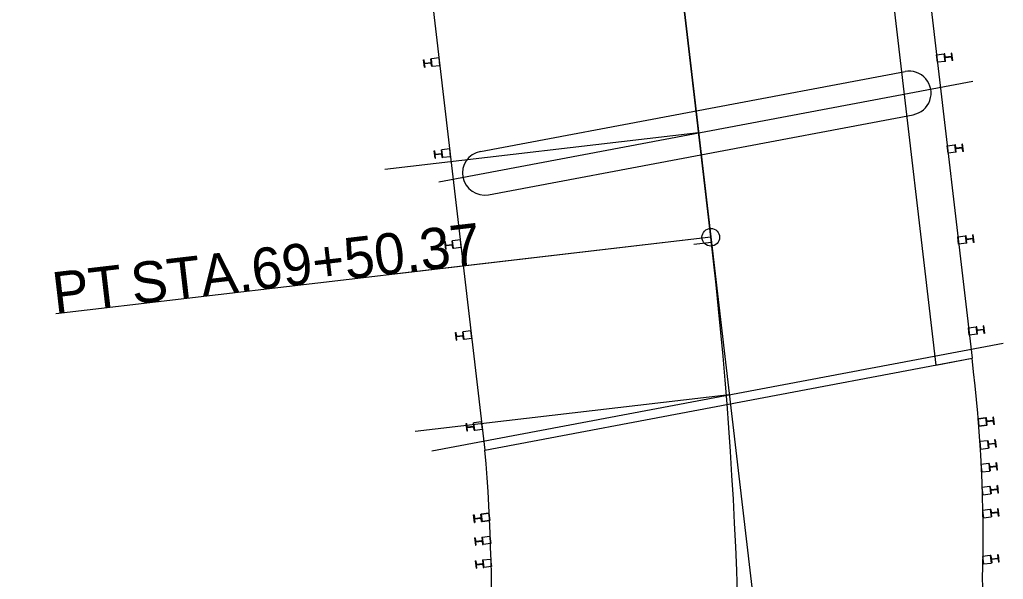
# Model space of a CAD drawing. Extents: x 27625 to 127752, y 6088 to 302357.
# Drawn here: x 127685.2 to 127752.3, y 301985 to 302023.2 of the extents above; entities that cross this region are included whole.
import ezdxf

# ---------------------------------------------------------------- set-up
doc = ezdxf.new("R2010")
doc.units = 0
for name, color, linetype in [('_CIVIL_CONSTRUCTION', 7, 'Continuous'), ('DR_X_Cells', 7, 'Continuous'), ('DV_X_Property_Line', 7, 'Continuous'), ('DV_X_Section_VMS_Line', 7, 'Continuous'), ('RW_X_CL', 7, 'Continuous'), ('RW_X_CL_100_Bearings', 7, 'Continuous'), ('RW_X_CL_100_Cardinal_Points', 7, 'Continuous'), ('RW_X_CL_100_Curve_Data', 7, 'Continuous'), ('RW_X_CL_100_Stations', 7, 'Continuous'), ('RW_X_Fee_RW', 7, 'Continuous'), ('SC_Scratch13', 7, 'Continuous'), ('SC_Scratch2', 7, 'Continuous'), ('SV_X_Mon_Cells_Found', 7, 'Continuous'), ('TopoDOT_Transients', 7, 'Continuous')]:
    doc.layers.add(name, color=color, linetype=linetype)

msp = doc.modelspace()

# ---------------------------------------------------------------- linework, layer by layer
at = {"layer": '_CIVIL_CONSTRUCTION'}
for p, q in [((127731.494, 302015.492), (127710.068, 302012.985)), ((127733.585, 301997.613), (127712.159, 301995.107))]:
    msp.add_line(p, q, dxfattribs=at)
at = {"layer": 'DR_X_Cells'}
msp.add_line((127732.371, 302007.993), (127731.179, 302007.855), dxfattribs=at)
msp.add_line((127732.371, 302007.993), (127731.179, 302007.855), dxfattribs=at)
at = {"layer": 'DV_X_Property_Line'}
for p, q in [((127743.217, 302059.446), (127750.158, 302000.104)), ((127709.97, 302053.181), (127716.911, 301993.839))]:
    msp.add_line(p, q, dxfattribs=at)
at = {"layer": 'DV_X_Section_VMS_Line'}
msp.add_line((127726.789, 302055.717), (127735.28, 301983.124), dxfattribs=at)
at = {"layer": 'RW_X_CL'}
for p, q in [((127716.6, 302014.211), (127745.586, 302019.673)), ((127717.156, 302011.263), (127746.141, 302016.725))]:
    msp.add_line(p, q, dxfattribs=at)
for centre, start, end in [((127745.864, 302018.199), 280.67141, 100.67141), ((127716.878, 302012.737), 100.67141, 280.67141)]:
    msp.add_arc(centre, 1.5, start, end, dxfattribs=at)
at = {"layer": 'RW_X_CL_100_Bearings'}
msp.add_line((127716.911, 301993.839), (127750.158, 302000.104), dxfattribs=at)
for centre, radius, start, end in [((127649.647, 301987.699), 101.274, 358.48079, 7.0357), ((127591.889, 301983.136), 125.479, 357.96645, 4.89308)]:
    msp.add_arc(centre, radius, start, end, dxfattribs=at)
at = {"layer": 'RW_X_CL_100_Cardinal_Points'}
msp.add_arc((127439.051, 301974.056), 312.026, 359.36547, 2.01244, dxfattribs=at)
at = {"layer": 'RW_X_CL_100_Curve_Data'}
for p, q in [((127747.736, 302020.81), (127748.264, 302020.872)), ((127748.3, 302020.876), (127748.264, 302020.872)), ((127748.323, 302020.365), (127748.264, 302020.872)), ((127748.324, 302020.669), (127748.3, 302020.876)), ((127748.752, 302020.688), (127748.358, 302020.642)), ((127748.755, 302020.657), (127748.362, 302020.611)), ((127748.791, 302020.934), (127748.755, 302020.929)), ((127748.779, 302020.722), (127748.755, 302020.929)), ((127748.85, 302020.427), (127748.791, 302020.934)), ((127712.726, 302020.471), (127712.762, 302020.475)), ((127712.785, 302019.964), (127712.726, 302020.471)), ((127712.786, 302020.268), (127712.762, 302020.475)), ((127712.785, 302019.964), (127712.821, 302019.968)), ((127712.821, 302019.968), (127712.797, 302020.175)), ((127712.821, 302020.241), (127713.214, 302020.287)), ((127712.825, 302020.209), (127713.218, 302020.255)), ((127713.217, 302020.528), (127713.254, 302020.532)), ((127713.242, 302020.321), (127713.217, 302020.528)), ((127713.277, 302020.021), (127713.252, 302020.228)), ((127713.781, 302020.594), (127713.254, 302020.532)), ((127713.313, 302020.025), (127713.254, 302020.532)), ((127713.277, 302020.021), (127713.313, 302020.025)), ((127713.313, 302020.025), (127713.84, 302020.087)), ((127748.323, 302020.365), (127747.795, 302020.303)), ((127748.359, 302020.369), (127748.323, 302020.365)), ((127748.359, 302020.369), (127748.335, 302020.576)), ((127748.814, 302020.422), (127748.79, 302020.629)), ((127748.85, 302020.427), (127748.814, 302020.422)), ((127748.462, 302014.602), (127748.99, 302014.664)), ((127749.026, 302014.668), (127748.99, 302014.664)), ((127749.049, 302014.157), (127748.99, 302014.664)), ((127749.05, 302014.461), (127749.026, 302014.668)), ((127749.517, 302014.726), (127749.481, 302014.722)), ((127749.505, 302014.515), (127749.481, 302014.722)), ((127749.576, 302014.219), (127749.517, 302014.726)), ((127713.452, 302014.263), (127713.488, 302014.267)), ((127713.511, 302013.756), (127713.452, 302014.263)), ((127713.512, 302014.06), (127713.488, 302014.267)), ((127713.548, 302013.76), (127713.523, 302013.967)), ((127713.547, 302014.033), (127713.94, 302014.079)), ((127713.551, 302014.002), (127713.944, 302014.048)), ((127713.943, 302014.32), (127713.98, 302014.325)), ((127713.968, 302014.113), (127713.943, 302014.32)), ((127714.003, 302013.813), (127713.979, 302014.02)), ((127714.507, 302014.386), (127713.98, 302014.325)), ((127714.039, 302013.818), (127713.98, 302014.325)), ((127749.049, 302014.157), (127748.521, 302014.096)), ((127749.085, 302014.162), (127749.049, 302014.157)), ((127749.085, 302014.162), (127749.061, 302014.368)), ((127749.478, 302014.48), (127749.085, 302014.434)), ((127749.482, 302014.449), (127749.088, 302014.403)), ((127749.54, 302014.215), (127749.516, 302014.422)), ((127749.576, 302014.219), (127749.54, 302014.215)), ((127713.511, 302013.756), (127713.548, 302013.76)), ((127714.003, 302013.813), (127714.039, 302013.818)), ((127714.039, 302013.818), (127714.567, 302013.879)), ((127714.178, 302008.055), (127714.214, 302008.059)), ((127714.237, 302007.548), (127714.178, 302008.055)), ((127714.239, 302007.853), (127714.214, 302008.059)), ((127714.67, 302008.113), (127714.706, 302008.117)), ((127714.694, 302007.906), (127714.67, 302008.113)), ((127715.233, 302008.179), (127714.706, 302008.117)), ((127714.765, 302007.61), (127714.706, 302008.117)), ((127749.188, 302008.395), (127749.716, 302008.456)), ((127749.775, 302007.95), (127749.247, 302007.888)), ((127749.752, 302008.461), (127749.716, 302008.456)), ((127749.775, 302007.95), (127749.716, 302008.456)), ((127749.776, 302008.254), (127749.752, 302008.461)), ((127749.811, 302007.954), (127749.775, 302007.95)), ((127749.811, 302007.954), (127749.787, 302008.161)), ((127750.204, 302008.272), (127749.811, 302008.226)), ((127750.208, 302008.241), (127749.814, 302008.195)), ((127750.243, 302008.518), (127750.207, 302008.514)), ((127750.231, 302008.307), (127750.207, 302008.514)), ((127750.266, 302008.007), (127750.242, 302008.214)), ((127750.303, 302008.011), (127750.243, 302008.518)), ((127750.303, 302008.011), (127750.266, 302008.007)), ((127714.237, 302007.548), (127714.274, 302007.553)), ((127714.274, 302007.553), (127714.249, 302007.759)), ((127714.273, 302007.825), (127714.666, 302007.871)), ((127714.277, 302007.794), (127714.67, 302007.84)), ((127714.729, 302007.606), (127714.705, 302007.813)), ((127714.729, 302007.606), (127714.765, 302007.61)), ((127714.765, 302007.61), (127715.293, 302007.672)), ((127714.904, 302001.848), (127714.94, 302001.852)), ((127714.964, 302001.341), (127714.904, 302001.848)), ((127714.965, 302001.645), (127714.94, 302001.852)), ((127715.396, 302001.905), (127715.432, 302001.909)), ((127715.42, 302001.698), (127715.396, 302001.905)), ((127715.959, 302001.971), (127715.432, 302001.909)), ((127715.491, 302001.402), (127715.432, 302001.909)), ((127749.914, 302002.187), (127750.442, 302002.249)), ((127750.478, 302002.253), (127750.442, 302002.249)), ((127750.501, 302001.742), (127750.442, 302002.249)), ((127750.502, 302002.046), (127750.478, 302002.253)), ((127750.537, 302001.746), (127750.513, 302001.953)), ((127750.93, 302002.065), (127750.537, 302002.019)), ((127750.934, 302002.034), (127750.54, 302001.988)), ((127750.969, 302002.311), (127750.933, 302002.306)), ((127750.957, 302002.099), (127750.933, 302002.306)), ((127750.992, 302001.799), (127750.968, 302002.006)), ((127751.029, 302001.804), (127750.969, 302002.311)), ((127714.964, 302001.341), (127715, 302001.345)), ((127715, 302001.345), (127714.976, 302001.552)), ((127714.999, 302001.617), (127715.393, 302001.663)), ((127715.003, 302001.586), (127715.396, 302001.632)), ((127715.455, 302001.398), (127715.431, 302001.605)), ((127715.455, 302001.398), (127715.491, 302001.402)), ((127715.491, 302001.402), (127716.019, 302001.464)), ((127750.501, 302001.742), (127749.974, 302001.68)), ((127750.537, 302001.746), (127750.501, 302001.742)), ((127751.029, 302001.804), (127750.992, 302001.799)), ((127750.573, 301995.972), (127751.1, 301996.033)), ((127751.1, 301996.033), (127750.573, 301995.972)), ((127751.137, 301996.037), (127751.1, 301996.033)), ((127751.16, 301995.526), (127751.1, 301996.033)), ((127751.161, 301995.831), (127751.137, 301996.037)), ((127751.589, 301995.849), (127751.195, 301995.803)), ((127751.592, 301995.818), (127751.199, 301995.772)), ((127751.628, 301996.095), (127751.592, 301996.091)), ((127751.616, 301995.884), (127751.592, 301996.091)), ((127751.687, 301995.588), (127751.628, 301996.095)), ((127715.63, 301995.64), (127715.667, 301995.644)), ((127715.69, 301995.133), (127715.63, 301995.64)), ((127715.691, 301995.437), (127715.667, 301995.644)), ((127715.69, 301995.133), (127715.726, 301995.137)), ((127715.726, 301995.137), (127715.702, 301995.344)), ((127715.725, 301995.41), (127716.119, 301995.456)), ((127715.729, 301995.379), (127716.122, 301995.425)), ((127716.122, 301995.697), (127716.158, 301995.702)), ((127716.146, 301995.49), (127716.122, 301995.697)), ((127716.181, 301995.19), (127716.157, 301995.397)), ((127716.686, 301995.763), (127716.158, 301995.702)), ((127716.217, 301995.195), (127716.158, 301995.702)), ((127716.181, 301995.19), (127716.217, 301995.195)), ((127716.217, 301995.195), (127716.745, 301995.256)), ((127751.16, 301995.526), (127750.632, 301995.465)), ((127750.632, 301995.465), (127751.16, 301995.526)), ((127751.196, 301995.531), (127751.16, 301995.526)), ((127751.196, 301995.531), (127751.172, 301995.738)), ((127751.651, 301995.584), (127751.627, 301995.791)), ((127751.687, 301995.588), (127751.651, 301995.584)), ((127751.212, 301994.473), (127750.685, 301994.411)), ((127751.248, 301994.477), (127751.212, 301994.473)), ((127751.212, 301994.473), (127751.272, 301993.966)), ((127751.248, 301994.477), (127751.273, 301994.27)), ((127751.74, 301994.535), (127751.704, 301994.531)), ((127751.704, 301994.531), (127751.728, 301994.324)), ((127751.74, 301994.535), (127751.799, 301994.028)), ((127750.744, 301993.905), (127751.272, 301993.966)), ((127751.308, 301993.971), (127751.272, 301993.966)), ((127751.284, 301994.177), (127751.308, 301993.971)), ((127751.701, 301994.289), (127751.307, 301994.243)), ((127751.704, 301994.258), (127751.311, 301994.212)), ((127751.739, 301994.231), (127751.763, 301994.024)), ((127751.799, 301994.028), (127751.763, 301994.024)), ((127751.3, 301992.91), (127750.772, 301992.849)), ((127751.336, 301992.915), (127751.3, 301992.91)), ((127751.3, 301992.91), (127751.359, 301992.403)), ((127751.336, 301992.915), (127751.36, 301992.708)), ((127751.371, 301992.615), (127751.395, 301992.408)), ((127751.788, 301992.726), (127751.395, 301992.68)), ((127751.792, 301992.695), (127751.399, 301992.649)), ((127751.828, 301992.972), (127751.791, 301992.968)), ((127751.791, 301992.968), (127751.816, 301992.761)), ((127751.826, 301992.668), (127751.851, 301992.461)), ((127751.828, 301992.972), (127751.887, 301992.465)), ((127751.887, 301992.465), (127751.851, 301992.461)), ((127750.832, 301992.342), (127751.359, 301992.403)), ((127751.395, 301992.408), (127751.359, 301992.403)), ((127751.364, 301991.345), (127750.836, 301991.283)), ((127751.4, 301991.349), (127751.364, 301991.345)), ((127751.364, 301991.345), (127751.423, 301990.838)), ((127751.4, 301991.349), (127751.424, 301991.142)), ((127751.852, 301991.161), (127751.459, 301991.115)), ((127751.856, 301991.129), (127751.462, 301991.083)), ((127751.891, 301991.406), (127751.855, 301991.402)), ((127751.855, 301991.402), (127751.879, 301991.195)), ((127751.89, 301991.102), (127751.914, 301990.895)), ((127751.891, 301991.406), (127751.951, 301990.899)), ((127750.895, 301990.776), (127751.423, 301990.838)), ((127751.459, 301990.842), (127751.423, 301990.838)), ((127751.435, 301991.049), (127751.459, 301990.842)), ((127751.951, 301990.899), (127751.914, 301990.895)), ((127751.403, 301989.776), (127750.876, 301989.714)), ((127751.439, 301989.78), (127751.403, 301989.776)), ((127751.403, 301989.776), (127751.462, 301989.269)), ((127751.439, 301989.78), (127751.463, 301989.573)), ((127751.931, 301989.838), (127751.895, 301989.834)), ((127751.895, 301989.834), (127751.919, 301989.627)), ((127751.931, 301989.838), (127751.99, 301989.331)), ((127716.133, 301989.406), (127716.169, 301989.41)), ((127716.133, 301989.406), (127716.169, 301989.41)), ((127716.192, 301988.899), (127716.133, 301989.406)), ((127716.133, 301989.406), (127716.192, 301988.899)), ((127716.193, 301989.203), (127716.169, 301989.41)), ((127716.169, 301989.41), (127716.193, 301989.203)), ((127716.228, 301988.903), (127716.204, 301989.11)), ((127716.204, 301989.11), (127716.228, 301988.903)), ((127716.228, 301989.176), (127716.621, 301989.222)), ((127716.228, 301989.176), (127716.621, 301989.222)), ((127716.231, 301989.145), (127716.625, 301989.191)), ((127716.231, 301989.145), (127716.625, 301989.191)), ((127716.624, 301989.463), (127716.66, 301989.468)), ((127716.624, 301989.463), (127716.66, 301989.468)), ((127716.648, 301989.257), (127716.624, 301989.463)), ((127716.624, 301989.463), (127716.648, 301989.257)), ((127716.684, 301988.957), (127716.659, 301989.164)), ((127716.659, 301989.164), (127716.684, 301988.957)), ((127717.188, 301989.529), (127716.66, 301989.468)), ((127716.66, 301989.468), (127717.188, 301989.529)), ((127716.72, 301988.961), (127716.66, 301989.468)), ((127716.66, 301989.468), (127716.72, 301988.961)), ((127750.935, 301989.207), (127751.462, 301989.269)), ((127751.499, 301989.273), (127751.462, 301989.269)), ((127751.474, 301989.48), (127751.499, 301989.273)), ((127751.891, 301989.592), (127751.498, 301989.546)), ((127751.895, 301989.561), (127751.502, 301989.515)), ((127751.93, 301989.534), (127751.954, 301989.327)), ((127751.99, 301989.331), (127751.954, 301989.327)), ((127716.192, 301988.899), (127716.228, 301988.903)), ((127716.192, 301988.899), (127716.228, 301988.903)), ((127716.684, 301988.957), (127716.72, 301988.961)), ((127716.684, 301988.957), (127716.72, 301988.961)), ((127716.72, 301988.961), (127717.247, 301989.023)), ((127717.247, 301989.023), (127716.72, 301988.961)), ((127716.2, 301987.841), (127716.236, 301987.845)), ((127716.2, 301987.841), (127716.259, 301987.334)), ((127716.236, 301987.845), (127716.26, 301987.638)), ((127716.691, 301987.898), (127716.727, 301987.902)), ((127716.691, 301987.898), (127716.715, 301987.691)), ((127716.727, 301987.902), (127717.255, 301987.964)), ((127716.727, 301987.902), (127716.787, 301987.395)), ((127716.259, 301987.334), (127716.295, 301987.338)), ((127716.271, 301987.545), (127716.295, 301987.338)), ((127716.295, 301987.611), (127716.688, 301987.657)), ((127716.298, 301987.58), (127716.692, 301987.626)), ((127716.726, 301987.598), (127716.75, 301987.391)), ((127716.75, 301987.391), (127716.787, 301987.395)), ((127717.314, 301987.457), (127716.787, 301987.395)), ((127716.775, 301986.335), (127717.302, 301986.396)), ((127751.409, 301986.63), (127750.881, 301986.569)), ((127751.445, 301986.635), (127751.409, 301986.63)), ((127751.409, 301986.63), (127751.468, 301986.124)), ((127751.445, 301986.635), (127751.469, 301986.428)), ((127751.897, 301986.446), (127751.504, 301986.4)), ((127751.901, 301986.415), (127751.508, 301986.369)), ((127751.937, 301986.692), (127751.9, 301986.688)), ((127751.9, 301986.688), (127751.925, 301986.481)), ((127751.937, 301986.692), (127751.996, 301986.185)), ((127716.247, 301986.273), (127716.283, 301986.277)), ((127716.247, 301986.273), (127716.306, 301985.766)), ((127716.283, 301986.277), (127716.307, 301986.07)), ((127716.306, 301985.766), (127716.343, 301985.77)), ((127716.318, 301985.977), (127716.343, 301985.77)), ((127716.342, 301986.043), (127716.735, 301986.089)), ((127716.346, 301986.012), (127716.739, 301986.058)), ((127716.739, 301986.331), (127716.775, 301986.335)), ((127716.739, 301986.331), (127716.763, 301986.124)), ((127716.774, 301986.031), (127716.798, 301985.824)), ((127716.775, 301986.335), (127716.834, 301985.828)), ((127716.798, 301985.824), (127716.834, 301985.828)), ((127717.362, 301985.89), (127716.834, 301985.828)), ((127750.941, 301986.062), (127751.468, 301986.124)), ((127751.504, 301986.128), (127751.468, 301986.124)), ((127751.48, 301986.335), (127751.504, 301986.128)), ((127751.935, 301986.388), (127751.96, 301986.181)), ((127751.996, 301986.185), (127751.96, 301986.181))]:
    msp.add_line(p, q, dxfattribs=at)
for centre, start, end in [((127748.355, 302020.673), 186.67141, 276.67141), ((127748.748, 302020.719), 276.67141, 6.67141), ((127748.759, 302020.626), 6.67141, 96.67141), ((127712.817, 302020.272), 186.67141, 276.67141), ((127712.828, 302020.178), 96.67141, 186.67141), ((127713.211, 302020.318), 276.67141, 6.67141), ((127713.222, 302020.224), 6.67141, 96.67141), ((127748.366, 302020.58), 96.67141, 186.67141), ((127713.543, 302014.064), 186.67141, 276.67141), ((127713.554, 302013.971), 96.67141, 186.67141), ((127713.937, 302014.11), 276.67141, 6.67141), ((127713.948, 302014.017), 6.67141, 96.67141), ((127749.081, 302014.465), 186.67141, 276.67141), ((127749.092, 302014.372), 96.67141, 186.67141), ((127749.474, 302014.511), 276.67141, 6.67141), ((127749.485, 302014.418), 6.67141, 96.67141), ((127714.663, 302007.902), 276.67141, 6.67141), ((127749.807, 302008.257), 186.67141, 276.67141), ((127749.818, 302008.164), 96.67141, 186.67141), ((127750.2, 302008.303), 276.67141, 6.67141), ((127750.211, 302008.21), 6.67141, 96.67141), ((127714.27, 302007.856), 186.67141, 276.67141), ((127714.28, 302007.763), 96.67141, 186.67141), ((127714.674, 302007.809), 6.67141, 96.67141), ((127750.533, 302002.05), 186.67141, 276.67141), ((127750.544, 302001.957), 96.67141, 186.67141), ((127750.926, 302002.096), 276.67141, 6.67141), ((127750.937, 302002.003), 6.67141, 96.67141), ((127714.996, 302001.649), 186.67141, 276.67141), ((127715.007, 302001.555), 96.67141, 186.67141), ((127715.389, 302001.695), 276.67141, 6.67141), ((127715.4, 302001.601), 6.67141, 96.67141), ((127751.192, 301995.834), 186.67141, 276.67141), ((127751.585, 301995.88), 276.67141, 6.67141), ((127751.596, 301995.787), 6.67141, 96.67141), ((127715.722, 301995.441), 186.67141, 276.67141), ((127715.733, 301995.348), 96.67141, 186.67141), ((127716.115, 301995.487), 276.67141, 6.67141), ((127716.126, 301995.394), 6.67141, 96.67141), ((127751.203, 301995.741), 96.67141, 186.67141), ((127751.304, 301994.274), 186.67141, 276.67141), ((127751.314, 301994.181), 96.67141, 186.67141), ((127751.697, 301994.32), 276.67141, 6.67141), ((127751.708, 301994.227), 6.67141, 96.67141), ((127751.391, 301992.711), 186.67141, 276.67141), ((127751.402, 301992.618), 96.67141, 186.67141), ((127751.785, 301992.757), 276.67141, 6.67141), ((127751.795, 301992.664), 6.67141, 96.67141), ((127751.455, 301991.146), 186.67141, 276.67141), ((127751.848, 301991.191), 276.67141, 6.67141), ((127751.859, 301991.098), 6.67141, 96.67141), ((127751.466, 301991.052), 96.67141, 186.67141), ((127716.224, 301989.207), 186.67141, 276.67141), ((127716.224, 301989.207), 186.67141, 276.67141), ((127716.235, 301989.114), 96.67141, 186.67141), ((127716.235, 301989.114), 96.67141, 186.67141), ((127716.617, 301989.253), 276.67141, 6.67141), ((127716.617, 301989.253), 276.67141, 6.67141), ((127716.628, 301989.16), 6.67141, 96.67141), ((127716.628, 301989.16), 6.67141, 96.67141), ((127751.494, 301989.577), 186.67141, 276.67141), ((127751.505, 301989.484), 96.67141, 186.67141), ((127751.888, 301989.623), 276.67141, 6.67141), ((127751.899, 301989.53), 6.67141, 96.67141), ((127716.291, 301987.642), 186.67141, 276.67141), ((127716.302, 301987.549), 96.67141, 186.67141), ((127716.684, 301987.688), 276.67141, 6.67141), ((127716.695, 301987.595), 6.67141, 96.67141), ((127751.5, 301986.431), 186.67141, 276.67141), ((127751.894, 301986.477), 276.67141, 6.67141), ((127751.904, 301986.384), 6.67141, 96.67141), ((127716.338, 301986.074), 186.67141, 276.67141), ((127716.349, 301985.981), 96.67141, 186.67141), ((127716.732, 301986.12), 276.67141, 6.67141), ((127716.743, 301986.027), 6.67141, 96.67141), ((127751.511, 301986.338), 96.67141, 186.67141)]:
    msp.add_arc(centre, 0.0312, start, end, dxfattribs=at)
at = {"layer": 'RW_X_CL_100_Stations'}
for p, q in [((127747.795, 302020.303), (127747.736, 302020.81)), ((127713.84, 302020.087), (127713.781, 302020.594)), ((127748.521, 302014.096), (127748.462, 302014.602)), ((127714.567, 302013.879), (127714.507, 302014.386)), ((127715.293, 302007.672), (127715.233, 302008.179)), ((127749.247, 302007.888), (127749.188, 302008.395)), ((127716.019, 302001.464), (127715.959, 302001.971)), ((127749.974, 302001.68), (127749.914, 302002.187)), ((127750.632, 301995.465), (127750.573, 301995.972)), ((127750.573, 301995.972), (127750.632, 301995.465)), ((127716.745, 301995.256), (127716.686, 301995.763)), ((127750.685, 301994.411), (127750.744, 301993.905)), ((127750.772, 301992.849), (127750.832, 301992.342)), ((127750.836, 301991.283), (127750.895, 301990.776)), ((127717.247, 301989.023), (127717.188, 301989.529)), ((127717.188, 301989.529), (127717.247, 301989.023)), ((127750.876, 301989.714), (127750.935, 301989.207)), ((127717.255, 301987.964), (127717.314, 301987.457)), ((127717.302, 301986.396), (127717.362, 301985.89)), ((127750.881, 301986.569), (127750.941, 301986.062))]:
    msp.add_line(p, q, dxfattribs=at)
at = {"layer": 'RW_X_Fee_RW'}
for p, q in [((127713.765, 302012.151), (127750.205, 302019.017)), ((127713.28, 301993.787), (127752.296, 302001.139))]:
    msp.add_line(p, q, dxfattribs=at)
at = {"layer": 'SC_Scratch13'}
msp.add_line((127732.328, 302008.36), (127691.71, 302355.623), dxfattribs=at)
msp.add_arc((127439.051, 301974.056), 295.276, 326.45641, 6.67141, dxfattribs=at)
at = {"layer": 'SC_Scratch2'}
msp.add_line((127732.328, 302008.36), (127710.902, 302005.854), dxfattribs=at)
msp.add_line((127732.328, 302008.36), (127710.902, 302005.854), dxfattribs=at)
at = {"layer": 'SV_X_Mon_Cells_Found'}
msp.add_line((127732.328, 302008.36), (127687.633, 302003.132), dxfattribs=at)
msp.add_line((127732.328, 302008.36), (127687.633, 302003.132), dxfattribs=at)
msp.add_circle((127732.328, 302008.36), 0.6, dxfattribs=at)
msp.add_circle((127732.328, 302008.36), 0.6, dxfattribs=at)
at = {"layer": 'TopoDOT_Transients'}
for p, q in [((127740.754, 302058.982), (127747.695, 301999.639)), ((127743.217, 302059.446), (127750.158, 302000.104)), ((127747.695, 301999.639), (127750.158, 302000.104))]:
    msp.add_line(p, q, dxfattribs=at)

# ---------------------------------------------------------------- texts
at = {"layer": 'SV_X_Mon_Cells_Found'}
for s, p in [('69+50.37', (127701.14, 302004.749)), (' STA. ', (127691.881, 302003.666)), ('PT', (127687.559, 302003.161))]:
    msp.add_text(s, height=2.8, rotation=6.67141, dxfattribs=at).set_placement(p)

doc.saveas('drawing.dxf')
